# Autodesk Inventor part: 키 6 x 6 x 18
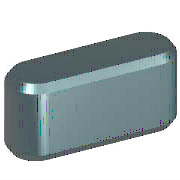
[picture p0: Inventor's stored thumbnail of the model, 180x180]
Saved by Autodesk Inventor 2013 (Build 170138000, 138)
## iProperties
IsCustomPart: 1
Created: 2012-02
Part Number: 키 6 x 6 x 18
Material: 강철, 연강
Description: 키 및 해당 키홈
Document SubType Name: Modeling
Standard: KS B 1311
Designer: mduedu
Standards Organization: KS
Language: ko-KR
Size Designation: 6 x 6 x 18
Categories: <MemberInstance><Categories><Category DisplayName="샤프트 부품" InternalName="7f7aeb1f-a693-4053-b835-cee3144e0d98" Mnemonic="SHFT"><Category DisplayName="키" Interna
Density: 1 g/cm^3
Author: mduedu
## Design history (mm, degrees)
workplane "Work Plane1"
workplane "Work Plane2"
sketch "스케치1"
  geometry: L1 (3, 3)-(15, 3); L2 (15, -3)-(3, -3); L3 (0, 9.4)-(0, -7.4) reference; L4 (-5, 0)-(30, 0) reference; L5 (18, 0)-(18, 7); A1 r 3 centre (3, 0) between (3, 3) and (3, -3); A2 r 3 centre (15, 0) between (15, -3) and (15, 3)
  constraints: 6 end point, 5 point on circle, 4 tangent, 3 point on line, 2 centre point, 1 horizontal, 1 parallel, 1 perpendicular
  dimensions: "d0" = 3 radius of A1 (= 0.5 x PB); "d13" = 3 radius of A2 (= 0.5 x PB); "d14" = 18 distance between parallel lines of L5 L3 (= NLG)
extrude "본체1" new body sketch "스케치1" taper "d3" = 0 deg; stored distance "d4" = 10
workplane "Work Plane3"
body "Solid1"
chamfer "모따기1" distance "d8" = 0.4 (= PHH); stored, may be unused: second distance "d9" = 0.4 (= PHH), angle "d15" = 45 deg
other parameters: "d1" = -3.5 (= -PNT), "d2" = 2.5 (= PH - PNT), "NLG" = 18 [user parameter; used in 3 equation terms], "PB" = 6 [user parameter; used in 2 equation terms], "PNT" = 3.5 [user parameter; used in 2 equation terms], "PH" = 6 [user parameter; used in 1 equation term], "PHH" = 0.4 [user parameter; used in 2 equation terms], "d10" = 0, "d16" = 0, "d17" = 0, "d18" = 0, "WDMIN" = 17 [user parameter], "PLB2" = 18 (= NLG) [user parameter], "WDMAX" = 22 [user parameter], "PLB1" = 18 (= NLG) [user parameter], "RR" = 0.16 [user parameter], "PUEB" = 2.8 [user parameter]
